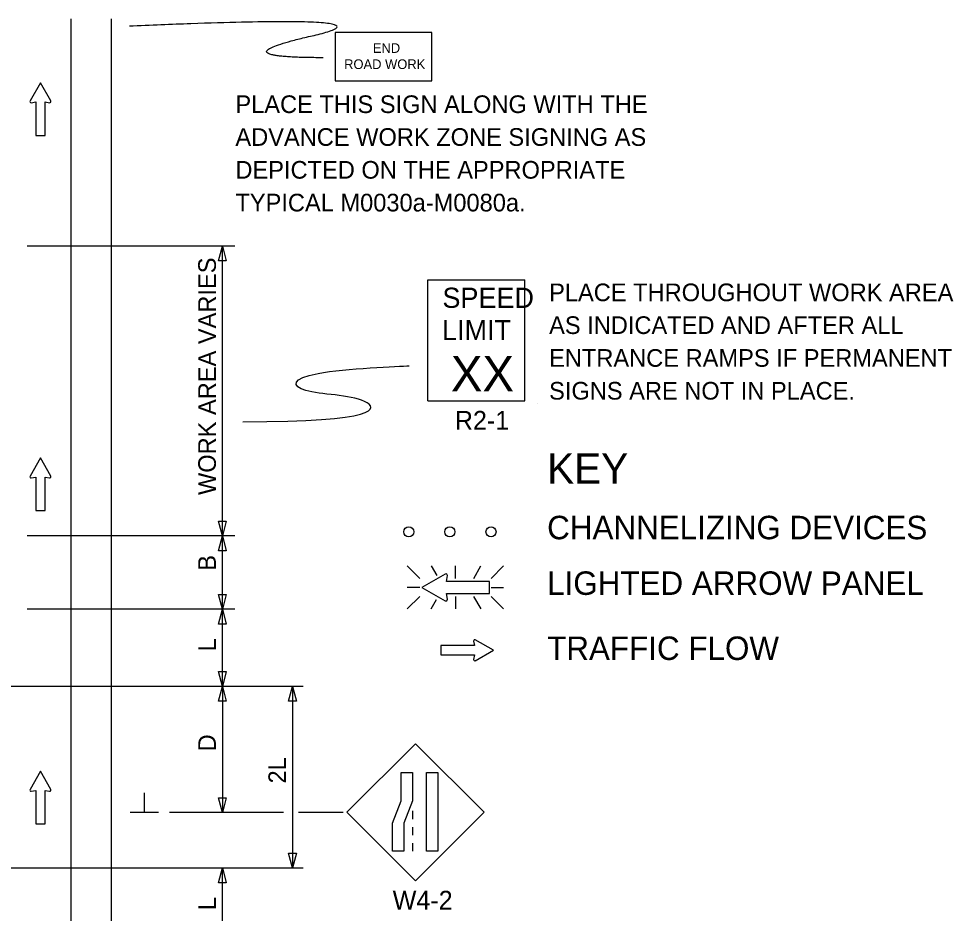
# Model space of a CAD drawing. Extents: x 16794 to 19504, y 7009 to 8243.
# Drawn here: x 18083.7 to 18454, y 7860.1 to 8214.7 of the extents above; entities that cross this region are included whole.
import ezdxf

# ---------------------------------------------------------------- set-up
doc = ezdxf.new("R2010")
doc.units = 0
for name, color, linetype in [('MT_SCRATCH_LEVEL_E', 7, 'Continuous'), ('PAVT_EDGE_EX', 7, 'Continuous'), ('TRAFFIC_SIGNS_PR', 7, 'Continuous'), ('TYPICAL_TEXT_DIMEN_EX', 7, 'Continuous'), ('TYPICAL_TEXT_DIMEN_PR', 7, 'Continuous')]:
    doc.layers.add(name, color=color, linetype=linetype)

msp = doc.modelspace()

# ---------------------------------------------------------------- linework, layer by layer
at = {"layer": 'MT_SCRATCH_LEVEL_E'}
for p, q in [((18092.27, 8189.32), (18088.15, 8182.08)), ((18096.41, 8182.08), (18092.27, 8189.32)), ((18088.64, 8181.39), (18090.41, 8181.71)), ((18090.41, 8181.71), (18090.41, 8168.45)), ((18094.16, 8168.45), (18094.16, 8181.71)), ((18094.16, 8181.71), (18095.93, 8181.39)), ((18090.41, 8168.45), (18094.16, 8168.45)), ((18092.27, 8040.64), (18088.15, 8033.4)), ((18096.41, 8033.4), (18092.27, 8040.64)), ((18088.64, 8032.72), (18090.41, 8033.03)), ((18090.41, 8033.03), (18090.41, 8019.77)), ((18094.16, 8019.77), (18094.16, 8033.03)), ((18094.16, 8033.03), (18095.93, 8032.72)), ((18090.41, 8019.77), (18094.16, 8019.77)), ((18264.24, 7966.23), (18250.98, 7966.23)), ((18250.98, 7966.23), (18250.98, 7962.49)), ((18263.92, 7968.01), (18264.24, 7966.23)), ((18271.85, 7964.38), (18264.6, 7968.49)), ((18250.98, 7962.49), (18264.24, 7962.49)), ((18264.24, 7962.49), (18263.92, 7960.71)), ((18264.6, 7960.23), (18271.85, 7964.38)), ((18092.27, 7916.38), (18088.15, 7909.14)), ((18096.41, 7909.14), (18092.27, 7916.38)), ((18088.64, 7908.46), (18090.41, 7908.77)), ((18090.41, 7908.77), (18090.41, 7895.52)), ((18094.16, 7895.52), (18094.16, 7908.77)), ((18094.16, 7908.77), (18095.93, 7908.46)), ((18090.41, 7895.52), (18094.16, 7895.52))]:
    msp.add_line(p, q, dxfattribs=at)
for centre, start, end in [((18088.56, 8181.85), 150.4248, 279.9638), ((18096, 8181.85), 260.0362, 29.7731), ((18088.56, 8033.18), 150.4248, 279.9638), ((18096, 8033.18), 260.0362, 29.7731), ((18264.38, 7968.08), 60.4248, 189.9638), ((18264.38, 7960.64), 170.0362, 299.7731), ((18088.56, 7908.92), 150.4248, 279.9638), ((18096, 7908.92), 260.0362, 29.7731)]:
    msp.add_arc(centre, 0.463, start, end, dxfattribs=at)
at = {"layer": 'PAVT_EDGE_EX'}
for p, q in [((18104.37, 8214.7), (18104.37, 7554.34)), ((18120.37, 8214.7), (18120.37, 7554.34))]:
    msp.add_line(p, q, dxfattribs=at)
at = {"layer": 'TRAFFIC_SIGNS_PR'}
for p, q in [((18245.81, 8111.22), (18284.21, 8111.22)), ((18245.81, 8063.22), (18245.81, 8111.22)), ((18284.21, 8063.22), (18284.21, 8111.22)), ((18245.81, 8063.22), (18284.21, 8063.22)), ((18237.66, 7997.76), (18242.59, 7992.83)), ((18249.42, 7993.94), (18247.21, 7997.77)), ((18256.74, 7992.83), (18256.74, 7997.77)), ((18263.98, 7992.83), (18266.83, 7997.77)), ((18270.89, 7992.83), (18275.83, 7997.77)), ((18242.59, 7989.27), (18237.66, 7989.27)), ((18270.89, 7989.27), (18275.83, 7989.27)), ((18237.66, 7980.79), (18242.59, 7985.72)), ((18256.74, 7985.72), (18256.74, 7980.78)), ((18266.87, 7980.78), (18264.02, 7985.72)), ((18270.89, 7985.72), (18275.83, 7980.78)), ((18247.17, 7980.78), (18249.28, 7984.45)), ((18240.91, 7927.33), (18213.75, 7900.17)), ((18268.06, 7900.17), (18240.91, 7927.33)), ((18213.75, 7900.17), (18240.91, 7873.02)), ((18239.66, 7900.66), (18239.66, 7897.46)), ((18240.91, 7873.02), (18268.06, 7900.17)), ((18239.66, 7894.26), (18239.66, 7891.06)), ((18239.66, 7887.86), (18239.66, 7884.66))]:
    msp.add_line(p, q, dxfattribs=at)
for points in [[(18209.01, 8190.01), (18247.41, 8190.01), (18247.41, 8209.21), (18209.01, 8209.21)], [(18239.66, 7915.91), (18239.66, 7904.73), (18236.32, 7895.85), (18236.32, 7884.66), (18231.82, 7884.66), (18231.82, 7895.85), (18235.17, 7904.73), (18235.17, 7915.91)], [(18249.8, 7915.91), (18249.8, 7884.66), (18245.3, 7884.66), (18245.3, 7915.91)]]:
    msp.add_lwpolyline(points, close=True, dxfattribs=at)
for points in [[(18252.67, 7994.55), (18243.38, 7989.27), (18252.67, 7983.95)], [(18253.54, 7984.58), (18253.14, 7986.85), (18270.16, 7986.85), (18270.16, 7991.65), (18253.14, 7991.65), (18253.55, 7993.93)]]:
    msp.add_lwpolyline(points, dxfattribs=at)
for centre in [(18238.22, 8011.31), (18254.52, 8011.31), (18270.82, 8011.31)]:
    msp.add_circle(centre, 2, dxfattribs=at)
for centre, radius, start, end in [((18252.96, 7994.03), 0.598, 350.7308, 118.8916), ((18252.96, 7984.48), 0.597, 241.4833, 9.9593)]:
    msp.add_arc(centre, radius, start, end, dxfattribs=at)
msp.add_open_spline([(18204.29, 8199.24), (18161.78, 8199.24), (18238.3, 8216.65), (18127.51, 8211.71)], degree=2, dxfattribs=at)
at = {"layer": 'TYPICAL_TEXT_DIMEN_PR'}
for p, q in [((18169.37, 8124.58), (18086.97, 8124.58)), ((18162.8, 8118.72), (18164.37, 8124.58)), ((18164.37, 8009.67), (18164.37, 8124.58)), ((18164.37, 8124.58), (18165.94, 8118.72)), ((18164.37, 8118.72), (18162.8, 8118.72)), ((18165.94, 8118.72), (18164.37, 8118.72)), ((18164.37, 8009.67), (18162.8, 8015.53)), ((18162.8, 8015.53), (18164.37, 8015.53)), ((18164.37, 8015.53), (18165.94, 8015.53)), ((18165.94, 8015.53), (18164.37, 8009.67)), ((18169.37, 8009.67), (18086.97, 8009.67)), ((18162.8, 8003.81), (18164.37, 8009.67)), ((18164.37, 7980.62), (18164.37, 8009.67)), ((18164.37, 8009.67), (18165.94, 8003.81)), ((18164.37, 8003.81), (18162.8, 8003.81)), ((18165.94, 8003.81), (18164.37, 8003.81)), ((18164.37, 7980.62), (18162.8, 7986.48)), ((18162.8, 7986.48), (18164.37, 7986.48)), ((18164.37, 7986.48), (18165.94, 7986.48)), ((18165.94, 7986.48), (18164.37, 7980.62)), ((18169.37, 7980.62), (18086.97, 7980.62)), ((18162.8, 7974.75), (18164.37, 7980.62)), ((18164.37, 7950.05), (18164.37, 7980.62)), ((18164.37, 7980.62), (18165.94, 7974.75)), ((18164.37, 7974.75), (18162.8, 7974.75)), ((18165.94, 7974.75), (18164.37, 7974.75)), ((18164.37, 7950.05), (18162.8, 7955.91)), ((18162.8, 7955.91), (18164.37, 7955.91)), ((18164.37, 7955.91), (18165.94, 7955.91)), ((18165.94, 7955.91), (18164.37, 7950.05)), ((18196.41, 7950.05), (18065.26, 7950.05)), ((18162.8, 7944.19), (18164.37, 7950.05)), ((18164.37, 7950.05), (18164.37, 7900.05)), ((18164.37, 7950.05), (18165.94, 7944.19)), ((18190.6, 7944.19), (18192.17, 7950.05)), ((18192.17, 7950.05), (18193.74, 7944.19)), ((18192.17, 7950.05), (18192.17, 7878.05)), ((18164.37, 7944.19), (18162.8, 7944.19)), ((18165.94, 7944.19), (18164.37, 7944.19)), ((18192.17, 7944.19), (18190.6, 7944.19)), ((18193.74, 7944.19), (18192.17, 7944.19)), ((18133.49, 7900.05), (18133.49, 7907.84)), ((18164.37, 7900.05), (18162.8, 7905.91)), ((18162.8, 7905.91), (18164.37, 7905.91)), ((18164.37, 7905.91), (18165.94, 7905.91)), ((18165.94, 7905.91), (18164.37, 7900.05)), ((18192.17, 7904.92), (18192.17, 7901.15)), ((18139.12, 7900.05), (18127.87, 7900.05)), ((18188.54, 7900.05), (18143.37, 7900.05)), ((18212.25, 7900.05), (18194.55, 7900.05)), ((18199.51, 7900.05), (18199.25, 7900.05)), ((18192.17, 7878.05), (18190.6, 7883.91)), ((18190.6, 7883.91), (18192.17, 7883.91)), ((18192.17, 7883.91), (18193.74, 7883.91)), ((18193.74, 7883.91), (18192.17, 7878.05)), ((18065.26, 7878.05), (18196.41, 7878.05)), ((18162.8, 7872.19), (18164.37, 7878.05)), ((18164.37, 7847.49), (18164.37, 7878.05)), ((18164.37, 7878.05), (18165.94, 7872.19)), ((18164.37, 7872.19), (18162.8, 7872.19)), ((18165.94, 7872.19), (18164.37, 7872.19))]:
    msp.add_line(p, q, dxfattribs=at)
for points, degree in [([(18172.48, 8054.93), (18226.54, 8054.93), (18226.54, 8065.68), (18191.62, 8065.68), (18191.62, 8075.35), (18234.48, 8076.87), (18238.37, 8077.13)], 3), ([(18289.32, 8062.34), (18289.34, 8062.34), (18289.34, 8062.34), (18289.34, 8062.34)], 2)]:
    msp.add_open_spline(points, degree=degree, dxfattribs=at)

# ---------------------------------------------------------------- texts
at = {"layer": 'TRAFFIC_SIGNS_PR'}
for s, height, p in [('END', 3.831, (18224.01, 8201.14)), ('ROAD WORK', 3.831, (18212.62, 8194.75)), ('PLACE THIS SIGN ALONG WITH THE', 7, (18169.54, 8177.3)), ('ADVANCE WORK ZONE SIGNING AS', 7, (18169.54, 8164.3)), ('DEPICTED ON THE APPROPRIATE', 7, (18169.54, 8151.3)), ('TYPICAL M0030a-M0080a.', 7, (18169.54, 8138.3)), ('SPEED', 8, (18251.57, 8100.08)), ('PLACE THROUGHOUT WORK AREA', 7, (18293.84, 8102.72)), ('AS INDICATED AND AFTER ALL', 7, (18293.84, 8089.72)), ('LIMIT', 8, (18251.41, 8087.28)), ('XX', 14.031, (18254.92, 8066.97)), ('ENTRANCE RAMPS IF PERMANENT', 7, (18293.84, 8076.72)), ('SIGNS ARE NOT IN PLACE.', 7, (18293.84, 8063.72)), ('R2-1', 7.44, (18256.48, 8051.78)), ('W4-2', 7.44, (18231.86, 7861.58))]:
    msp.add_text(s, height=height, dxfattribs=at).set_placement(p)
at = {"layer": 'TYPICAL_TEXT_DIMEN_EX'}
for s, height, p in [('KEY', 12, (18293.06, 8030.41)), ('CHANNELIZING DEVICES', 9.3, (18293.06, 8008.36)), ('LIGHTED ARROW PANEL', 9.3, (18293.06, 7986.31)), ('TRAFFIC FLOW', 9.3, (18293.06, 7960.51))]:
    msp.add_text(s, height=height, dxfattribs=at).set_placement(p)
at = {"layer": 'TYPICAL_TEXT_DIMEN_PR'}
for s, p in [('WORK AREA VARIES', (18161.81, 8025.89)), ('B', (18161.81, 7995.88)), ('L', (18161.81, 7963.91)), ('D', (18161.81, 7924.27)), ('2L', (18189.61, 7911.55)), ('L', (18161.81, 7861.34))]:
    msp.add_text(s, height=7, rotation=90, dxfattribs=at).set_placement(p)

doc.saveas('drawing.dxf')
